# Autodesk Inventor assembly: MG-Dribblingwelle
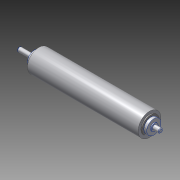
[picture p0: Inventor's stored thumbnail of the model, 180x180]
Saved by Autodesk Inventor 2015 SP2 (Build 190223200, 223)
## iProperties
Created: 2012-07
Part Number: MG-Dribblingwelle
Document SubType Name: Assembly
Designer: rYan
Mass: 21.0348 g
Surface Area: 72.0072 cm^2
Volume: 8.45505 cm^3
Density: 2.48783 g/cm^3
Author: rYan
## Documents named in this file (4)
- E:\TIGERs GIT\Hardware\mechanik\2016\Inventor\Dribbling Device\MG-Dribblingwelle.iam
- E:\TIGERs GIT\Hardware\mechanik\2016\Inventor\Dribbling Device\Dribblingwelle.ipt
- E:\TIGERs GIT\Hardware\mechanik\2016\Inventor\Dribbling Device\Gummischlauch.ipt
- E:\TIGERs GIT\Hardware\mechanik\2016\Inventor\Inhaltscenter\de-DE\DIN 6799\DIN 6799 - 6 7.ipt
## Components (4 placed, 3 different names)
1. Dribblingwelle:1 — Passend:2, Passend:4, Einfügen:1
2. Gummischlauch:1 — Einfügen:1
3. DIN 6799 6:1 — Passend:2
4. DIN 6799 6:2 — Passend:4
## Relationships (3: Mate 2, Insert 1)
- Passend:2 [Mate]: Dribblingwelle:1 ↔ DIN 6799 6:1
- Passend:4 [Mate]: Dribblingwelle:1 ↔ DIN 6799 6:2
- Einfügen:1 [Insert]: Dribblingwelle:1 ↔ Gummischlauch:1
